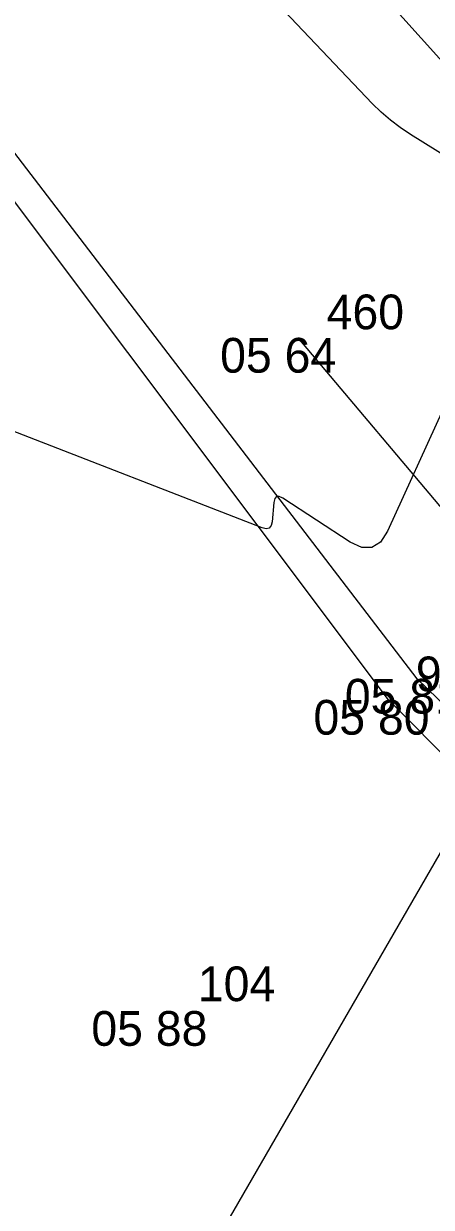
# Model space of a CAD drawing. Extents: x -711234 to -710007, y -1026313 to -1025448.
# Drawn here: x -711048.26 to -711044.96, y -1025879.27 to -1025869.72 of the extents above; entities that cross this region are included whole.
import ezdxf

# ---------------------------------------------------------------- set-up
doc = ezdxf.new("R2010")
doc.units = 0
for name, color, linetype in [('Ex_Minor Contours', 7, 'Continuous'), ('Z_body', 7, 'Continuous'), ('Z_body_cisla', 7, 'Continuous'), ('Z_body_vysky_redukovane', 7, 'Continuous'), ('Z_komunikace', 7, 'Continuous'), ('Z_propustek', 7, 'Continuous'), ('Z_vdz25_plna', 7, 'Continuous'), ('Z_zabradli', 7, 'Continuous'), ('Z_zlabek', 7, 'Continuous')]:
    doc.layers.add(name, color=color, linetype=linetype)

# ---------------------------------------------------------------- blocks, each defined once
blk = doc.blocks.new('POINT_DISPLAY')
blk.add_line((0, 0), (0, 0))

msp = doc.modelspace()

# ---------------------------------------------------------------- linework, layer by layer
at = {"layer": 'Ex_Minor Contours'}
for points in [[(-711044.6915, -1025870.892), (-711045.1336, -1025870.6182), (-711045.2166, -1025870.563), (-711045.2955, -1025870.503), (-711045.3705, -1025870.4379), (-711045.4414, -1025870.3679), (-711048.8412, -1025866.7925)], [(-711044.8682, -1025872.8356), (-711045.3182, -1025873.8194), (-711045.3749, -1025873.9074), (-711045.4443, -1025873.9513), (-711045.5265, -1025873.9512), (-711045.6214, -1025873.9071), (-711046.164, -1025873.5525), (-711046.1929, -1025873.5387), (-711046.2145, -1025873.54), (-711046.2289, -1025873.5562), (-711046.2361, -1025873.5874), (-711046.2503, -1025873.7421), (-711046.2579, -1025873.7742), (-711046.2737, -1025873.7931), (-711046.2977, -1025873.7989), (-711046.3298, -1025873.7914), (-711050.5484, -1025872.1572)]]:
    msp.add_lwpolyline(points, dxfattribs=at)
at = {"layer": 'Z_komunikace'}
for p, q in [((-711045.08, -1025875.01), (-711048.91, -1025870.01)), ((-711040.31, -1025879.63), (-711045.08, -1025875.01))]:
    msp.add_line(p, q, dxfattribs=at)
at = {"layer": 'Z_propustek'}
msp.add_line((-711053.28, -1025890.92), (-711042.93, -1025873.02), dxfattribs=at)
at = {"layer": 'Z_vdz25_plna'}
for p, q in [((-711045.31, -1025875.18), (-711049.18, -1025870.03)), ((-711040.59, -1025879.94), (-711045.31, -1025875.18))]:
    msp.add_line(p, q, dxfattribs=at)
at = {"layer": 'Z_zabradli'}
msp.add_line((-711042.26, -1025876.74), (-711046.04, -1025872.26), dxfattribs=at)
at = {"layer": 'Z_zlabek'}
msp.add_line((-711044.32, -1025870.65), (-711049.18, -1025865.24), dxfattribs=at)

# ---------------------------------------------------------------- block references
at = {"layer": 'Z_body'}
for p in [(-711046.04, -1025872.26), (-711045.08, -1025875.01), (-711045.31, -1025875.18), (-711047.08, -1025877.69)]:
    msp.add_blockref('POINT_DISPLAY', p, dxfattribs=at)

# ---------------------------------------------------------------- texts
at = {"layer": 'Z_body_cisla'}
for s, p in [('460', (-711045.81, -1025872.19)), ('91', (-711045.09, -1025875.11)), ('104', (-711046.85, -1025877.61))]:
    msp.add_text(s, height=0.28, dxfattribs=at).set_placement(p)
at = {"layer": 'Z_body_vysky_redukovane'}
for s, p in [('05 64', (-711046.67, -1025872.54)), ('05 81', (-711045.6633, -1025875.29)), ('05 80', (-711045.9167, -1025875.46)), ('05 88', (-711047.71, -1025877.97))]:
    msp.add_text(s, height=0.28, dxfattribs=at).set_placement(p)

doc.saveas('drawing.dxf')
